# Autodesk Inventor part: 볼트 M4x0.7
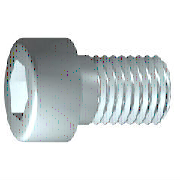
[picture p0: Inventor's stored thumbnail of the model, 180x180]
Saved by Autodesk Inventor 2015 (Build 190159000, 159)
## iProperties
IsCustomPart: 1
Created: 2015-10
Part Number: 볼트 M4x0.7
Material: 스테인리스강
Description: 6각머리 태핑 나사
Document SubType Name: Modeling
Standard: KS B 1003
Designer: mdu
Standards Organization: KS
Language: ko-KR
Size Designation: M 4 x 16
Categories: <MemberInstance><Categories><Category DisplayName="조임쇠" InternalName="e4da775c-781d-43d5-af7c-5136215cf5a6" Mnemonic="FSTN"><Category DisplayName="볼트" InternalN
Density: 8.08 g/cm^3
Mass: 2.70334 g
Surface Area: 3.81118 cm^2
Volume: 0.334572 cm^3
Appearance: 반광택
Author: mdu
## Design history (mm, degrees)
sketch "스케치1"
  geometry: L1 (-1, 0)-(14, 0); L2 (14, 0)-(14, 2); L3 (14, 2)-(1.75, 2); L4 (1.75, 2)-(1.32, 2); L5 (1.32, 2)-(0, 2); L6 (0, 2)-(0, 3.5); L7 (0, 3.5)-(-4, 3.5); L8 (-4, 3.5)-(-4, 1.732); L9 (-4, 1.732)-(-2, 1.732); L10 (-2, 1.732)-(-1, 0); L11 (-7.6, 0)-(17.6, 0) reference; L12 (0, -0.7)-(0, 4.2) reference; L13 (1.75, 2)-(0, 2)
  constraints: 22 end point, 6 parallel, 2 collinear, 2 perpendicular, 1 horizontal, 1 point on line
  dimensions: "d1" = 12.25 distance from line of L3.end L2 (= GEL); "d2" = 0.42952 distance of L4.end L3.end (computed from GAL); "d3" = 4 distance between parallel lines of L8 L6 (= KOH); "d4" = 2 distance of L8.end L9.end (= INTI); "d5" = 60 deg angle of L10 L1; "d6" = 4 diameter of L3 L1 (= GD); "d7" = 4 diameter of L5 L1 (= BDM); "d8" = 3.4641 diameter of L9 L1 (= 1.1547 x SW); "d9" = 7 diameter of L7 L1 (= KOD); "d26" = 14 distance between parallel lines of L12 L2 (= NLG)
revolve "본체" sketch "스케치1" stored, may be unused: angle "d10" = 90 deg
sketch "스케치2"
  geometry: L1 (0, -4.9)-(0, 4.9) reference; L2 (-4.9, 0)-(4.9, 0) reference; L3 (1.732, 0)-(0.866, -1.5); L4 (0.866, -1.5)-(-0.866, -1.5); L5 (-0.866, -1.5)-(-1.732, 0); L6 (-1.732, 0)-(-0.866, 1.5); L7 (-0.866, 1.5)-(0.866, 1.5); L8 (0.866, 1.5)-(1.732, 0); 2 further points
  constraints: 12 end point, 1 coincident, 1 horizontal alignment, 1 point on line, 12 other
extrude "슬롯" join sketch "스케치2" stored distance "d11" = 10; taper "d12" = 0 deg
workplane "Work Plane1"
fillet "Fillet2" dims "d30" = 0.1 (= R)
body "Solid1"
fillet "모깎기1" dims "d17" = 0.4 (= RR)
feature "스레드" dims "d13" = 12.25 (= GEL), "d14" = 0
chamfer "모따기1" distance "d15" = 0.42941 (= -0.5 x SPD + 0.5 x GD); stored, may be unused: second distance "d16" = 0.42941 (= GUL), angle "d27" = 45 deg
other parameters: "GD" = 4 (= NND) [user parameter; used in 2 equation terms], "NLG" = 14 [user parameter; used in 1 equation term], "GEL" = 12.25 [user parameter; used in 2 equation terms], "KOD" = 7 [user parameter; used in 1 equation term], "KOH" = 4 [user parameter; used in 1 equation term], "INTI" = 2 [user parameter; used in 1 equation term], "GAL" = 0.42941 (= 0.61345 x PTC) [user parameter; used in 1 equation term], "GUL" = 0.42941 (= 0.61345 x PTC) [user parameter; used in 1 equation term], "BDM" = 4 (= NND) [user parameter; used in 1 equation term], "SW" = 3 [user parameter; used in 2 equation terms], "RR" = 0.4 [user parameter; used in 1 equation term], "SPD" = 3.14117 (= NND - 1.2269 x PTC) [user parameter; used in 1 equation term], "d19" = 0, "d28" = 0, "d29" = 0, "R" = 0.1 [user parameter; used in 1 equation term], "PHH" = 0.2 [user parameter], "GD1" = 3.14117 (= THREADDIA - 1.2269 x PTC) [user parameter], "THREADDIA" = 4 [user parameter; used in 1 equation term], "FAWI" = 45 deg [user parameter], "TPU" = 14.28571 (computed from PTC) [user parameter], "PTC" = 0.7 [user parameter; used in 5 equation terms], "NND" = 4 [user parameter; used in 3 equation terms], "TOA" = 30 deg [user parameter], "E0" = 3.465 (= 1.155 x SW) [user parameter]
